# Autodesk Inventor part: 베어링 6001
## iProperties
IsCustomPart: 0
Created: 2015-10
Part Number: 베어링 6001
Material: 강, 연강
Description: 깊은 그루브 볼 베어링
Document SubType Name: Modeling
Standard: KS B 2023
Designer: mdu
Standards Organization: KS
Language: ko-KR
Size Designation: 6001 - 12 x 28 x 8
Categories: <MemberInstance><Categories><Category DisplayName="샤프트 부품" InternalName="7f7aeb1f-a693-4053-b835-cee3144e0d98" Mnemonic="SHFT"><Category DisplayName="베어링" Inter
Density: 1 g/cm^3
Author: mdu
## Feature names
1. IDS_ARRAYBALL[SIMPL:T] [Circular Pattern]
